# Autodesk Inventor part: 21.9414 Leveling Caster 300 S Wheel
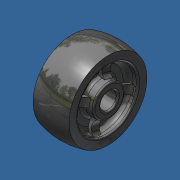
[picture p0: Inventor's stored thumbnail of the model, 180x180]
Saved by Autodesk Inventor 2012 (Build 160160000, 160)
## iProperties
Created: 2015-01
Part Number: 21.9414 Leveling Caster 300 S Wheel
Material: Phenolic
Document SubType Name: Modeling
Designer: Admin
Density: 1.38 g/cm^3
Mass: 44.3209 g
Surface Area: 95.2629 cm^2
Volume: 32.1166 cm^3
Author: Admin
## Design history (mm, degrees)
feature "Base1"
body "Solid1"
